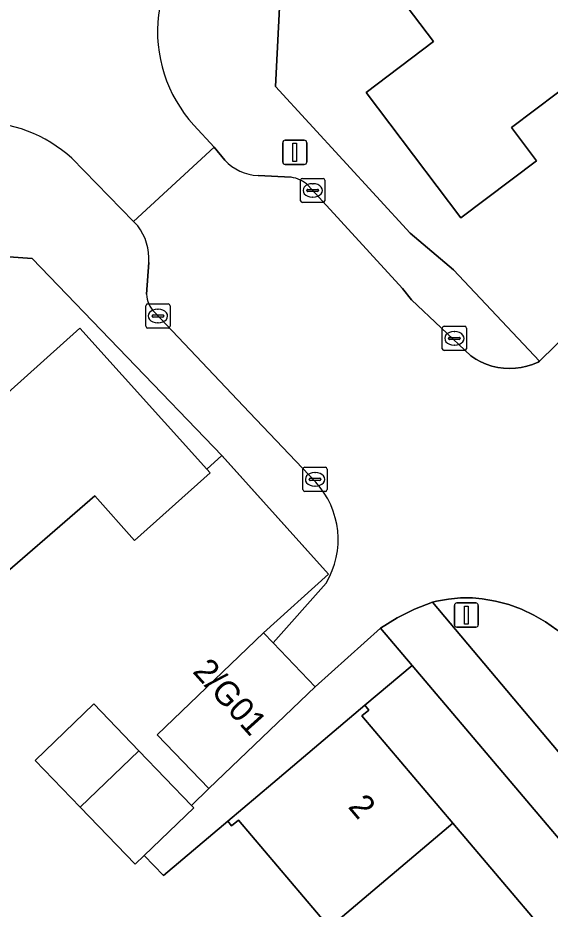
# Model space of a CAD drawing. Extents: x 157445 to 158888, y 383061 to 384688.
# Drawn here: x 158056 to 158078.02, y 383682.54 to 383719.45 of the extents above; entities that cross this region are included whole.
import ezdxf

# ---------------------------------------------------------------- set-up
doc = ezdxf.new("R2010")
doc.units = 0
for name, color, linetype in [('IMGEO_Erf', 7, 'Continuous'), ('IMGEO_Groenvoorziening', 7, 'Continuous'), ('IMGEO_Kolk', 7, 'Continuous'), ('IMGEO_Lichtmast', 7, 'Continuous'), ('IMGEO_Muur', 7, 'Continuous'), ('IMGEO_Pand', 7, 'Continuous'), ('IMGEO_Pand_nummerreeks', 7, 'Continuous'), ('IMGEO_Rijbaan_lokaal_open', 7, 'Continuous'), ('IMGEO_Voetpad_open', 7, 'Continuous')]:
    doc.layers.add(name, color=color, linetype=linetype)

msp = doc.modelspace()

# ---------------------------------------------------------------- linework, layer by layer
at = {"layer": 'IMGEO_Erf'}
for points in [[(158085.977, 383722.114), (158081.173, 383718.488), (158076.419, 383714.899), (158077.455, 383713.526), (158074.328, 383711.165), (158070.408, 383716.358), (158073.195, 383718.462), (158071.797, 383720.314)], [(158066.847, 383720.445), (158066.656, 383716.599), (158072.237, 383710.535), (158074.025, 383709.017), (158077.584, 383705.224), (158078.924, 383706.544), (158080.76, 383704.561), (158082.342, 383706.039), (158080.56, 383707.946), (158084.714, 383711.826), (158087.401, 383713.728), (158089.119, 383711.297), (158091.776, 383713.239), (158091.562, 383713.535), (158090.251, 383712.589), (158088.659, 383714.795), (158090.491, 383716.118), (158093.515, 383718.301), (158095.307, 383715.819), (158097.388, 383717.341), (158095.503, 383719.92)], [(158068.897, 383681.783), (158065.131, 383686.233), (158064.846, 383685.992), (158064.686, 383686.181), (158062.029, 383683.933), (158061.232, 383684.759), (158060.862, 383684.402), (158058.585, 383686.761), (158056.713, 383688.701), (158059.139, 383691.042), (158061.011, 383689.092), (158063.179, 383686.834), (158063.904, 383687.532), (158061.766, 383689.76), (158066.165, 383693.981), (158068.858, 383696.409), (158064.449, 383701.315), (158056.595, 383709.482), (158052.35, 383709.789), (158021.919, 383682.679), (158021.849, 383682.357)], [(158027.267, 383681.66), (158031.569, 383685.38), (158036.047, 383689.253), (158040.682, 383693.261), (158045.271, 383697.23), (158049.774, 383701.125), (158054.22, 383704.97), (158053.956, 383705.264), (158054.197, 383705.48), (158055.594, 383703.926), (158058.573, 383706.595), (158063.821, 383700.757), (158063.954, 383700.608), (158060.834, 383697.812), (158059.181, 383699.651), (158054.533, 383695.63), (158052.448, 383693.827), (158054.342, 383691.64), (158051.926, 383689.547), (158050.03, 383691.736), (158045.44, 383687.766), (158047.152, 383685.93), (158042.69, 383681.771)]]:
    msp.add_lwpolyline(points, dxfattribs=at)
msp.add_lwpolyline([(158072.313, 383692.636), (158070.36, 383690.983), (158070.525, 383690.787), (158070.237, 383690.543), (158074, 383686.097), (158077.829, 383681.572), (158081.783, 383676.9), (158085.593, 383672.397), (158089.505, 383667.775), (158093.355, 383663.225), (158093.632, 383663.46), (158093.805, 383663.256), (158095.722, 383664.977)], close=True, dxfattribs=at)
at = {"layer": 'IMGEO_Groenvoorziening'}
msp.add_lwpolyline([(158081.806, 383690.454), (158079.964, 383692.414), (158078.718, 383693.741), (158078.291, 383694.107), (158077.833, 383694.433), (158077.347, 383694.717), (158076.838, 383694.957), (158076.31, 383695.15), (158075.767, 383695.295), (158075.212, 383695.391), (158074.806, 383695.43), (158074.307, 383695.428), (158073.811, 383695.381), (158073.321, 383695.29), (158073.153, 383695.248), (158085.078, 383681.064), (158088.008, 383683.429)], close=True, dxfattribs=at)
at = {"layer": 'IMGEO_Kolk'}
for p, q in [((158067.699, 383711.873), (158067.699, 383712.725)), ((158067.774, 383712.799), (158068.626, 383712.799)), ((158068.7, 383712.725), (158068.7, 383711.873)), ((158068.001, 383712.342), (158068.399, 383712.342)), ((158068.187, 383712.579), (158068.212, 383712.579)), ((158067.958, 383712.293), (158067.958, 383712.305)), ((158068.396, 383712.256), (158067.998, 383712.256)), ((158068.21, 383712.019), (158068.185, 383712.019)), ((158068.442, 383712.305), (158068.442, 383712.293)), ((158068.626, 383711.799), (158067.774, 383711.799)), ((158061.372, 383707.599), (158062.224, 383707.599)), ((158061.297, 383706.673), (158061.297, 383707.525)), ((158061.785, 383707.379), (158061.81, 383707.379)), ((158062.298, 383707.525), (158062.298, 383706.673)), ((158061.556, 383707.093), (158061.556, 383707.105)), ((158061.994, 383707.056), (158061.596, 383707.056)), ((158061.599, 383707.142), (158061.997, 383707.142)), ((158061.808, 383706.819), (158061.783, 383706.819)), ((158062.04, 383707.105), (158062.04, 383707.093)), ((158062.224, 383706.599), (158061.372, 383706.599)), ((158073.559, 383705.748), (158073.559, 383706.6)), ((158073.634, 383706.674), (158074.486, 383706.674)), ((158074.047, 383706.454), (158074.072, 383706.454)), ((158074.56, 383706.6), (158074.56, 383705.748)), ((158073.818, 383706.168), (158073.818, 383706.18)), ((158074.256, 383706.131), (158073.858, 383706.131)), ((158073.861, 383706.217), (158074.259, 383706.217)), ((158074.302, 383706.18), (158074.302, 383706.168)), ((158074.07, 383705.894), (158074.045, 383705.894)), ((158074.486, 383705.674), (158073.634, 383705.674)), ((158067.795, 383699.912), (158067.795, 383700.764)), ((158067.87, 383700.838), (158068.722, 383700.838)), ((158068.283, 383700.618), (158068.308, 383700.618)), ((158068.796, 383700.764), (158068.796, 383699.912)), ((158068.054, 383700.332), (158068.054, 383700.344)), ((158068.492, 383700.295), (158068.094, 383700.295)), ((158068.097, 383700.381), (158068.495, 383700.381)), ((158068.538, 383700.344), (158068.538, 383700.332)), ((158068.722, 383699.838), (158067.87, 383699.838)), ((158068.306, 383700.058), (158068.281, 383700.058))]:
    msp.add_line(p, q, dxfattribs=at)
for points in [[(158067.699, 383711.873), (158067.699, 383712.725)], [(158067.774, 383712.799), (158068.626, 383712.799)], [(158068.7, 383712.725), (158068.7, 383711.873)], [(158068.626, 383711.799), (158067.774, 383711.799)], [(158061.372, 383707.599), (158062.224, 383707.599)], [(158061.297, 383706.673), (158061.297, 383707.525)], [(158062.298, 383707.525), (158062.298, 383706.673)], [(158062.224, 383706.599), (158061.372, 383706.599)], [(158073.559, 383705.748), (158073.559, 383706.6)], [(158073.634, 383706.674), (158074.486, 383706.674)], [(158074.56, 383706.6), (158074.56, 383705.748)], [(158074.486, 383705.674), (158073.634, 383705.674)], [(158067.795, 383699.912), (158067.795, 383700.764)], [(158067.87, 383700.838), (158068.722, 383700.838)], [(158068.796, 383700.764), (158068.796, 383699.912)], [(158068.722, 383699.838), (158067.87, 383699.838)]]:
    msp.add_lwpolyline(points, dxfattribs=at)
for centre, radius, start, end in [((158067.776, 383712.723), 0.0765, 91.552, 178.448), ((158067.776, 383712.723), 0.0765, 91.552, 178.448), ((158068.624, 383712.723), 0.0765, 1.552, 88.448), ((158068.624, 383712.723), 0.0765, 1.552, 88.448), ((158067.998, 383712.302), 0.0403, 85.8775, 175.7526), ((158068.403, 383712.304), 0.0386, 1.7309, 96.639), ((158067.995, 383712.292), 0.0366, 178.938, 274.7102), ((158068.399, 383712.299), 0.043, 264.8664, 352.4533), ((158067.776, 383711.875), 0.0765, 181.552, 268.448), ((158067.776, 383711.875), 0.0765, 181.552, 268.448), ((158068.624, 383711.875), 0.0765, 271.552, 358.448), ((158068.624, 383711.875), 0.0765, 271.552, 358.448), ((158061.374, 383707.523), 0.0765, 91.552, 178.448), ((158061.374, 383707.523), 0.0765, 91.552, 178.448), ((158062.222, 383707.523), 0.0765, 1.552, 88.448), ((158062.222, 383707.523), 0.0765, 1.552, 88.448), ((158061.596, 383707.102), 0.0403, 85.8775, 175.7526), ((158061.593, 383707.092), 0.0366, 178.938, 274.7102), ((158061.997, 383707.099), 0.043, 264.8664, 352.4533), ((158062.001, 383707.104), 0.0386, 1.7309, 96.639), ((158061.374, 383706.675), 0.0765, 181.552, 268.448), ((158061.374, 383706.675), 0.0765, 181.552, 268.448), ((158062.222, 383706.675), 0.0765, 271.552, 358.448), ((158062.222, 383706.675), 0.0765, 271.552, 358.448), ((158073.636, 383706.598), 0.0765, 91.552, 178.448), ((158073.636, 383706.598), 0.0765, 91.552, 178.448), ((158074.484, 383706.598), 0.0765, 1.552, 88.448), ((158074.484, 383706.598), 0.0765, 1.552, 88.448), ((158073.858, 383706.177), 0.0403, 85.8775, 175.7526), ((158073.855, 383706.167), 0.0366, 178.938, 274.7102), ((158074.259, 383706.174), 0.043, 264.8664, 352.4533), ((158074.263, 383706.179), 0.0386, 1.7309, 96.639), ((158073.636, 383705.75), 0.0765, 181.552, 268.448), ((158073.636, 383705.75), 0.0765, 181.552, 268.448), ((158074.484, 383705.75), 0.0765, 271.552, 358.448), ((158074.484, 383705.75), 0.0765, 271.552, 358.448), ((158067.872, 383700.762), 0.0765, 91.552, 178.448), ((158067.872, 383700.762), 0.0765, 91.552, 178.448), ((158068.72, 383700.762), 0.0765, 1.552, 88.448), ((158068.72, 383700.762), 0.0765, 1.552, 88.448), ((158068.094, 383700.341), 0.0403, 85.8775, 175.7526), ((158068.091, 383700.331), 0.0366, 178.938, 274.7102), ((158068.495, 383700.338), 0.043, 264.8664, 352.4533), ((158068.499, 383700.343), 0.0386, 1.7309, 96.639), ((158067.872, 383699.914), 0.0765, 181.552, 268.448), ((158067.872, 383699.914), 0.0765, 181.552, 268.448), ((158068.72, 383699.914), 0.0765, 271.552, 358.448), ((158068.72, 383699.914), 0.0765, 271.552, 358.448)]:
    msp.add_arc(centre, radius, start, end, dxfattribs=at)
for centre, major_axis, ratio, start_param, end_param in [((158068.186, 383712.299), (-0.387, 0.002), 0.722429, 4.712389, 7.853982), ((158068.211, 383712.299), (-0.39, 0.002), 0.717154, 1.570796, 4.712389), ((158061.784, 383707.099), (-0.387, 0.002), 0.722429, 4.712389, 7.853982), ((158061.809, 383707.099), (-0.39, 0.002), 0.717154, 1.570796, 4.712389), ((158074.046, 383706.174), (-0.387, 0.002), 0.722429, 4.712389, 7.853982), ((158074.071, 383706.174), (-0.39, 0.002), 0.717154, 1.570796, 4.712389), ((158068.282, 383700.338), (-0.387, 0.002), 0.722429, 4.712389, 7.853982), ((158068.307, 383700.338), (-0.39, 0.002), 0.717154, 1.570796, 4.712389)]:
    msp.add_ellipse(centre, major_axis=major_axis, ratio=ratio, start_param=start_param, end_param=end_param, dxfattribs=at)
at = {"layer": 'IMGEO_Lichtmast'}
for p, q in [((158066.962, 383713.476), (158066.962, 383714.276)), ((158066.962, 383714.276), (158066.962, 383713.476)), ((158067.062, 383714.376), (158067.852, 383714.376)), ((158067.852, 383714.376), (158067.062, 383714.376)), ((158067.952, 383714.276), (158067.952, 383713.476)), ((158067.952, 383713.476), (158067.952, 383714.276)), ((158067.852, 383713.376), (158067.062, 383713.376)), ((158067.062, 383713.376), (158067.852, 383713.376)), ((158074.06, 383694.318), (158074.06, 383695.118)), ((158074.06, 383695.118), (158074.06, 383694.318)), ((158074.16, 383695.218), (158074.95, 383695.218)), ((158074.95, 383695.218), (158074.16, 383695.218)), ((158075.05, 383695.118), (158075.05, 383694.318)), ((158075.05, 383694.318), (158075.05, 383695.118)), ((158074.95, 383694.218), (158074.16, 383694.218)), ((158074.16, 383694.218), (158074.95, 383694.218))]:
    msp.add_line(p, q, dxfattribs=at)
for points in [[(158067.382, 383714.251), (158067.532, 383714.251), (158067.532, 383713.501), (158067.382, 383713.501), (158067.382, 383714.251)], [(158074.48, 383695.093), (158074.63, 383695.093), (158074.63, 383694.343), (158074.48, 383694.343), (158074.48, 383695.093)]]:
    msp.add_lwpolyline(points, dxfattribs=at)
for centre, start, end in [((158067.062, 383714.276), 90, 180), ((158067.062, 383714.276), 90, 180), ((158067.852, 383714.276), 0, 90), ((158067.852, 383714.276), 360, 90), ((158067.062, 383713.476), 180, 270), ((158067.062, 383713.476), 180, 270), ((158067.852, 383713.476), 270, 0), ((158067.852, 383713.476), 270, 0), ((158074.16, 383695.118), 90, 180), ((158074.16, 383695.118), 90, 180), ((158074.95, 383695.118), 0, 90), ((158074.95, 383695.118), 360, 90), ((158074.16, 383694.318), 180, 270), ((158074.16, 383694.318), 180, 270), ((158074.95, 383694.318), 270, 0), ((158074.95, 383694.318), 270, 0)]:
    msp.add_arc(centre, 0.1, start, end, dxfattribs=at)
at = {"layer": 'IMGEO_Muur'}
for points in [[(158074.025, 383709.017), (158077.584, 383705.224)], [(158063.821, 383700.757), (158064.446, 383701.318)], [(158064.446, 383701.318), (158068.858, 383696.409)], [(158066.165, 383693.981), (158068.858, 383696.409)]]:
    msp.add_lwpolyline(points, dxfattribs=at)
at = {"layer": 'IMGEO_Pand'}
for points in [[(158081.173, 383718.488), (158077.158, 383723.821), (158072.365, 383720.203), (158072.106, 383720.547), (158071.797, 383720.314), (158073.195, 383718.462), (158070.408, 383716.358), (158074.328, 383711.165), (158077.455, 383713.526), (158076.419, 383714.899)], [(158058.573, 383706.595), (158055.594, 383703.926), (158054.197, 383705.48), (158053.956, 383705.264), (158054.22, 383704.97), (158049.774, 383701.125), (158054.533, 383695.63), (158059.181, 383699.651), (158060.834, 383697.812), (158063.954, 383700.608), (158063.821, 383700.757)], [(158068.304, 383691.753), (158066.557, 383693.572), (158066.165, 383693.981), (158061.766, 383689.76), (158063.904, 383687.532)], [(158056.713, 383688.701), (158058.585, 383686.761), (158061.011, 383689.092), (158059.139, 383691.042)], [(158074, 383686.097), (158070.237, 383690.543), (158070.525, 383690.787), (158070.36, 383690.983), (158066.544, 383687.753), (158064.686, 383686.181), (158064.846, 383685.992), (158065.131, 383686.233), (158068.897, 383681.783)], [(158061.011, 383689.092), (158058.585, 383686.761), (158060.862, 383684.402), (158061.232, 383684.759), (158063.277, 383686.732), (158063.179, 383686.834)], [(158072.726, 383677.258), (158077.829, 383681.572), (158074, 383686.097), (158068.897, 383681.783), (158067.259, 383680.398), (158071.078, 383675.88)]]:
    msp.add_lwpolyline(points, close=True, dxfattribs=at)
at = {"layer": 'IMGEO_Rijbaan_lokaal_open'}
for points in [[(158058.232, 383713.633), (158060.786, 383711.008), (158064.124, 383714.09), (158063.283, 383715.004)], [(158064.56, 383713.552), (158064.124, 383714.09), (158060.786, 383711.008), (158060.962, 383710.83)], [(158067.311, 383712.842), (158065.937, 383712.913)], [(158080.76, 383704.561), (158078.924, 383706.544), (158077.584, 383705.224), (158077.52, 383705.193), (158077.295, 383705.098), (158077.062, 383705.024), (158076.823, 383704.971), (158076.581, 383704.939), (158076.336, 383704.929), (158076.092, 383704.941), (158075.85, 383704.975), (158075.612, 383705.03), (158075.379, 383705.107), (158075.155, 383705.203), (158074.94, 383705.32), (158074.736, 383705.455), (158072.279, 383707.764), (158071.914, 383708.233), (158068.01, 383712.506)], [(158061.42, 383709.32), (158061.322, 383707.998)], [(158061.65, 383707.256), (158065.583, 383703.103), (158068.326, 383700.226)], [(158068.759, 383696.04), (158066.557, 383693.572), (158068.304, 383691.753), (158071.006, 383694.181), (158071.692, 383694.602), (158072.408, 383694.958), (158073.153, 383695.248), (158073.321, 383695.29), (158073.811, 383695.381), (158074.307, 383695.428), (158074.806, 383695.43), (158075.212, 383695.391), (158075.767, 383695.295), (158076.31, 383695.15), (158076.838, 383694.957), (158077.347, 383694.717), (158077.833, 383694.433), (158078.291, 383694.107)]]:
    msp.add_lwpolyline(points, dxfattribs=at)
for centre, radius, start, end in [((158067.516, 383718.875), 5.736, 123.6171, 222.4461), ((158054.425, 383709.481), 5.633, 47.4872, 91.4484), ((158066.03, 383714.916), 2.005, 222.8619, 267.3506), ((158067.148, 383711.608), 1.245, 46.1731, 82.4809), ((158059.209, 383709.474), 2.216, 356.0163, 37.73), ((158062.546, 383708.096), 1.228, 184.5559, 223.1396), ((158065.721, 383697.841), 3.531, 329.3328, 42.4785)]:
    msp.add_arc(centre, radius, start, end, dxfattribs=at)
at = {"layer": 'IMGEO_Voetpad_open'}
for points in [[(158068.01, 383712.506), (158071.914, 383708.233), (158072.279, 383707.764), (158074.736, 383705.455), (158074.94, 383705.32), (158075.155, 383705.203), (158075.379, 383705.107), (158075.612, 383705.03), (158075.85, 383704.975), (158076.092, 383704.941), (158076.336, 383704.929), (158076.581, 383704.939), (158076.823, 383704.971), (158077.062, 383705.024), (158077.295, 383705.098), (158077.52, 383705.193), (158077.584, 383705.224), (158074.025, 383709.017), (158072.237, 383710.535), (158066.656, 383716.599), (158066.847, 383720.445), (158089.464, 383737.55)], [(158054.283, 383715.112), (158052.35, 383709.789), (158056.595, 383709.482), (158064.449, 383701.315), (158068.858, 383696.409), (158066.165, 383693.981), (158066.557, 383693.572), (158068.759, 383696.04)], [(158063.283, 383715.004), (158064.124, 383714.09), (158064.56, 383713.552)], [(158060.962, 383710.83), (158060.786, 383711.008), (158058.232, 383713.633)], [(158065.937, 383712.913), (158067.311, 383712.842)], [(158061.322, 383707.998), (158061.42, 383709.32)], [(158068.326, 383700.226), (158065.583, 383703.103), (158061.65, 383707.256)], [(158090.443, 383674.723), (158093.643, 383677.531), (158092.902, 383678.334), (158089.769, 383675.56), (158086.414, 383679.474), (158089.434, 383681.946), (158088.008, 383683.429), (158085.078, 383681.064), (158073.153, 383695.248), (158072.408, 383694.958), (158071.692, 383694.602), (158071.006, 383694.181), (158072.313, 383692.636), (158095.722, 383664.977), (158093.805, 383663.256), (158092.782, 383662.391), (158094.707, 383660.115), (158094.951, 383660.322), (158095.138, 383660.101), (158094.937, 383659.925), (158095.792, 383658.433), (158105.581, 383641.442)]]:
    msp.add_lwpolyline(points, dxfattribs=at)
msp.add_lwpolyline([(158070.36, 383690.983), (158072.313, 383692.636), (158071.006, 383694.181), (158068.304, 383691.753), (158063.904, 383687.532), (158063.179, 383686.834), (158063.277, 383686.732), (158061.232, 383684.759), (158062.029, 383683.933), (158064.686, 383686.181), (158066.544, 383687.753)], close=True, dxfattribs=at)
for centre, radius, start, end in [((158067.516, 383718.875), 5.736, 123.6171, 222.4461), ((158054.425, 383709.481), 5.633, 47.4872, 91.4484), ((158066.03, 383714.916), 2.005, 222.8619, 267.3506), ((158067.148, 383711.608), 1.245, 46.1731, 82.4809), ((158059.209, 383709.474), 2.216, 356.0163, 37.73), ((158062.546, 383708.096), 1.228, 184.5559, 223.1396), ((158065.721, 383697.841), 3.531, 329.3328, 42.4785)]:
    msp.add_arc(centre, radius, start, end, dxfattribs=at)

# ---------------------------------------------------------------- texts
at = {"layer": 'IMGEO_Pand_nummerreeks'}
for s, rotation, p in [('2/G01', 311.9872, (158063.198, 383692.361)), ('2', 310.2167, (158069.63, 383686.767))]:
    msp.add_text(s, height=1, rotation=rotation, dxfattribs=at).set_placement(p)

doc.saveas('drawing.dxf')
